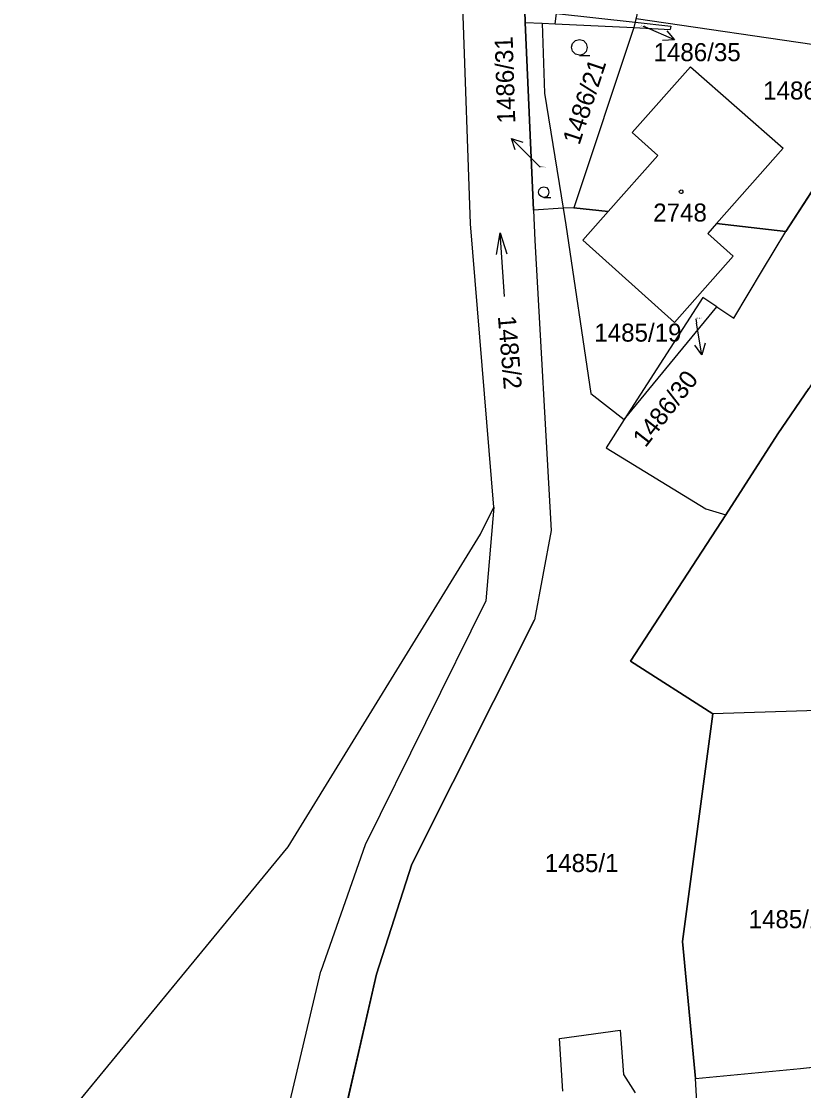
# Model space of a CAD drawing. Extents: x -779618 to -776429, y -1144546 to -1143350.
# Drawn here: x -777657.5 to -777583.8, y -1144048.7 to -1143948 of the extents above; entities that cross this region are included whole.
import ezdxf

# ---------------------------------------------------------------- set-up
doc = ezdxf.new("R2010")
doc.units = 0
for name, color, linetype in [('1', 7, 'Continuous'), ('11', 7, 'Continuous'), ('12', 7, 'Continuous'), ('2', 7, 'Continuous'), ('3', 7, 'Continuous'), ('5', 7, 'Continuous'), ('7', 7, 'Continuous')]:
    doc.layers.add(name, color=color, linetype=linetype)

msp = doc.modelspace()

# ---------------------------------------------------------------- linework, layer by layer
at = {"layer": '1'}
for p, q in [((-777615.23, -1143967.07), (-777615.93, -1143946.59)), ((-777610.06, -1143948.1), (-777610.11, -1143947)), ((-777609.28, -1143965.78), (-777610.06, -1143948.1)), ((-777610.06, -1143948.1), (-777608.45, -1143948.17)), ((-777608.45, -1143948.17), (-777608.24, -1143954.74)), ((-777608.45, -1143948.17), (-777607.23, -1143948.23)), ((-777607.23, -1143948.23), (-777599.81, -1143948.56)), ((-777599.7, -1143948.08), (-777599.81, -1143948.56)), ((-777599.61, -1143947.71), (-777574.85, -1143951.34)), ((-777599.81, -1143948.56), (-777605.49, -1143965.54)), ((-777599.81, -1143948.56), (-777596.4, -1143948.77)), ((-777599.98, -1143958.47), (-777594.47, -1143952.26)), ((-777594.47, -1143952.26), (-777585.75, -1143959.95)), ((-777574.85, -1143951.34), (-777585.5, -1143967.77)), ((-777608.24, -1143954.74), (-777606.48, -1143965.6)), ((-777597.55, -1143960.64), (-777599.98, -1143958.47)), ((-777585.75, -1143959.95), (-777592.03, -1143967.04)), ((-777602.23, -1143965.9), (-777597.55, -1143960.64)), ((-777606.48, -1143965.6), (-777609.28, -1143965.78)), ((-777609.28, -1143965.78), (-777609.16, -1143968.64)), ((-777605.49, -1143965.54), (-777606.48, -1143965.6)), ((-777606.48, -1143965.6), (-777606.23, -1143967.17)), ((-777602.23, -1143965.9), (-777605.49, -1143965.54)), ((-777604.63, -1143968.6), (-777602.23, -1143965.9)), ((-777613.01, -1143993.74), (-777615.23, -1143967.07)), ((-777606.23, -1143967.17), (-777603.89, -1143983.05)), ((-777592.03, -1143967.04), (-777592.85, -1143967.96)), ((-777585.5, -1143967.77), (-777592.03, -1143967.04)), ((-777592.85, -1143967.96), (-777590.45, -1143970.1)), ((-777587.69, -1143971.42), (-777585.5, -1143967.77)), ((-777609.16, -1143968.64), (-777607.6, -1143995.95)), ((-777595.99, -1143976.35), (-777604.63, -1143968.6)), ((-777590.45, -1143970.1), (-777595.99, -1143976.35)), ((-777590.41, -1143975.94), (-777587.69, -1143971.42)), ((-777593.33, -1143973.99), (-777600.73, -1143985.51)), ((-777592, -1143974.88), (-777593.33, -1143973.99)), ((-777600.73, -1143985.51), (-777592, -1143974.88)), ((-777592, -1143974.88), (-777590.41, -1143975.94)), ((-777603.89, -1143983.05), (-777600.73, -1143985.51)), ((-777586.26, -1143986.86), (-777583.34, -1143982.59)), ((-777600.73, -1143985.51), (-777602.44, -1143988.17)), ((-777591.14, -1143994.49), (-777586.26, -1143986.86)), ((-777602.44, -1143988.17), (-777593.04, -1143993.91)), ((-777614.26, -1143996.31), (-777613.01, -1143993.74)), ((-777613.01, -1143993.74), (-777613.76, -1144002.59)), ((-777600.14, -1144008.25), (-777591.14, -1143994.49)), ((-777593.04, -1143993.91), (-777591.14, -1143994.49)), ((-777632.39, -1144025.74), (-777614.26, -1143996.31)), ((-777607.6, -1143995.95), (-777609.19, -1144004.38)), ((-777613.76, -1144002.59), (-777625.14, -1144025.57)), ((-777620.75, -1144027.4), (-777609.19, -1144004.38)), ((-777592.38, -1144013.24), (-777600.14, -1144008.25)), ((-777595.25, -1144034.66), (-777592.38, -1144013.24)), ((-777580.39, -1144012.83), (-777592.38, -1144013.24)), ((-777657.54, -1144056.3), (-777632.39, -1144025.74)), ((-777625.14, -1144025.57), (-777629.33, -1144037.46)), ((-777624.08, -1144037.74), (-777620.75, -1144027.4)), ((-777594.01, -1144047.57), (-777595.25, -1144034.66)), ((-777633.19, -1144053.78), (-777629.33, -1144037.46)), ((-777627.73, -1144053.71), (-777624.08, -1144037.74)), ((-777606.82, -1144043.8), (-777601.12, -1144043.03)), ((-777606.52, -1144048.78), (-777606.82, -1144043.8)), ((-777601.12, -1144043.03), (-777600.8, -1144047.19)), ((-777584.12, -1144046.64), (-777575.18, -1144045.66)), ((-777594.01, -1144047.57), (-777584.12, -1144046.64)), ((-777600.8, -1144047.19), (-777599.69, -1144048.93)), ((-777593.88, -1144049.82), (-777594.01, -1144047.57))]:
    msp.add_line(p, q, dxfattribs=at)
for points in [[(-777607.23, -1143948.23), (-777607.11, -1143947.25), (-777599.7, -1143948.08)], [(-777599.7, -1143948.08), (-777596.35, -1143948.45), (-777596.4, -1143948.77)]]:
    msp.add_lwpolyline(points, dxfattribs=at)
at = {"layer": '11'}
msp.add_lwpolyline([(-777592.03, -1143967.04), (-777585.5, -1143967.77), (-777574.1, -1143950.18), (-777572.23, -1143946.4), (-777571.39, -1143943.64), (-777570.21, -1143938.03), (-777569.92, -1143933.75), (-777567.58, -1143916.99), (-777564.64, -1143899.27), (-777592.37, -1143895.2), (-777593.28, -1143913.19), (-777595.69, -1143931.03), (-777599.81, -1143948.56), (-777605.49, -1143965.54), (-777602.23, -1143965.9), (-777597.55, -1143960.64), (-777599.98, -1143958.47), (-777594.47, -1143952.26), (-777585.75, -1143959.95)], close=True, dxfattribs=at)
for points in [[(-777560.96, -1143943.75), (-777562.32, -1143948.83), (-777564.88, -1143954.4), (-777568.52, -1143960.36), (-777571.37, -1143964.42), (-777573.5, -1143967.56), (-777576.4, -1143971.94), (-777581.32, -1143979.45), (-777583.34, -1143982.59), (-777586.26, -1143986.86), (-777591.14, -1143994.49), (-777600.14, -1144008.25), (-777592.38, -1144013.24), (-777595.25, -1144034.66), (-777594.01, -1144047.57), (-777584.12, -1144046.64), (-777575.18, -1144045.66), (-777566.26, -1144044.71), (-777557.24, -1144043.82), (-777548.28, -1144042.89), (-777544.16, -1144042.52)], [(-777657.54, -1144056.3), (-777632.39, -1144025.74), (-777614.26, -1143996.31), (-777613.01, -1143993.74), (-777615.23, -1143967.07), (-777615.93, -1143946.59)], [(-777610.11, -1143947), (-777610.06, -1143948.1), (-777609.28, -1143965.78), (-777609.16, -1143968.64), (-777607.6, -1143995.95), (-777609.19, -1144004.38), (-777620.75, -1144027.4), (-777624.08, -1144037.74), (-777627.73, -1144053.71)]]:
    msp.add_lwpolyline(points, dxfattribs=at)
at = {"layer": '12'}
for p, q in [((-777599.98, -1143958.47), (-777594.47, -1143952.26)), ((-777594.47, -1143952.26), (-777585.75, -1143959.95)), ((-777597.55, -1143960.64), (-777599.98, -1143958.47)), ((-777585.75, -1143959.95), (-777592.03, -1143967.04)), ((-777602.23, -1143965.9), (-777597.55, -1143960.64)), ((-777604.63, -1143968.6), (-777602.23, -1143965.9)), ((-777592.03, -1143967.04), (-777592.85, -1143967.96)), ((-777592.85, -1143967.96), (-777590.45, -1143970.1)), ((-777595.99, -1143976.35), (-777604.63, -1143968.6)), ((-777590.45, -1143970.1), (-777595.99, -1143976.35))]:
    msp.add_line(p, q, dxfattribs=at)
at = {"layer": '3'}
msp.add_line((-777612, -1143973.9), (-777612.42, -1143967.92), dxfattribs=at)
for points in [[(-777604.94, -1143951.17), (-777605.32, -1143951.07), (-777605.59, -1143950.8), (-777605.69, -1143950.43), (-777605.59, -1143950.06), (-777605.32, -1143949.79), (-777604.95, -1143949.69), (-777604.58, -1143949.79), (-777604.31, -1143950.06), (-777604.21, -1143950.44), (-777604.31, -1143950.82), (-777604.58, -1143951.09), (-777604.96, -1143951.19), (-777603.96, -1143951.19)], [(-777608.31, -1143964.57), (-777608.56, -1143964.5), (-777608.75, -1143964.32), (-777608.81, -1143964.07), (-777608.75, -1143963.83), (-777608.56, -1143963.65), (-777608.32, -1143963.58), (-777608.07, -1143963.65), (-777607.89, -1143963.83), (-777607.82, -1143964.08), (-777607.89, -1143964.34), (-777608.07, -1143964.52), (-777608.32, -1143964.58), (-777607.65, -1143964.58)], [(-777612.78, -1143969.95), (-777612.42, -1143967.92), (-777611.78, -1143969.88)]]:
    msp.add_lwpolyline(points, dxfattribs=at)
at = {"layer": '5'}
msp.add_lwpolyline([(-777595.37, -1143963.87), (-777595.27, -1143963.89), (-777595.22, -1143963.98), (-777595.2, -1143964.04), (-777595.22, -1143964.13), (-777595.3, -1143964.2), (-777595.37, -1143964.21), (-777595.46, -1143964.18), (-777595.52, -1143964.12), (-777595.54, -1143964.04), (-777595.52, -1143963.95), (-777595.44, -1143963.88)], close=True, dxfattribs=at)
at = {"layer": '7'}
for p, q in [((-777598.96, -1143948.45), (-777598.74, -1143948.54)), ((-777595.99, -1143949.74), (-777598.74, -1143948.54)), ((-777611.35, -1143959.03), (-777609.23, -1143961.15)), ((-777608.65, -1143961.73), (-777609.23, -1143961.15)), ((-777593.98, -1143976), (-777593.91, -1143976.43)), ((-777593.43, -1143979.39), (-777593.91, -1143976.43))]:
    msp.add_line(p, q, dxfattribs=at)
for points in [[(-777596.71, -1143948.88), (-777595.99, -1143949.74), (-777597.11, -1143949.8)], [(-777611, -1143960.09), (-777611.35, -1143959.03), (-777610.29, -1143959.38)], [(-777593.1, -1143978.32), (-777593.43, -1143979.39), (-777594.08, -1143978.48)]]:
    msp.add_lwpolyline(points, dxfattribs=at)

# ---------------------------------------------------------------- texts
at = {"layer": '2'}
for s, height, p in [('1486/35', 0.1, (-777599.23, -1143948.45)), ('1486/22', 1.7, (-777587.64, -1143955.35)), ('1486/31', 0.1, (-777608.63, -1143961.73)), ('2748', 1.7, (-777598, -1143966.85)), ('1485/19', 1.7, (-777603.55, -1143978.16)), ('1486/30', 0.1, (-777593.96, -1143976)), ('1485/1', 1.7, (-777608.22, -1144028.13)), ('1485/13', 1.7, (-777589.01, -1144033.42))]:
    msp.add_text(s, height=height, dxfattribs=at).set_placement(p)
for s, rotation, p in [('1486/21', 71.8489, (-777604.96, -1143959.71)), ('1485/2', 274.7906, (-777612.64, -1143975.78))]:
    msp.add_text(s, height=1.7, rotation=rotation, dxfattribs=at).set_placement(p)
at = {"layer": '7'}
for s, rotation, p in [('1486/31', 91.7878, (-777610.99, -1143957.58)), ('1486/30', 51.9673, (-777598.73, -1143988.21))]:
    msp.add_text(s, height=1.7, rotation=rotation, dxfattribs=at).set_placement(p)
msp.add_text('1486/35', height=1.7, dxfattribs=at).set_placement((-777597.97, -1143951.74))

doc.saveas('drawing.dxf')
